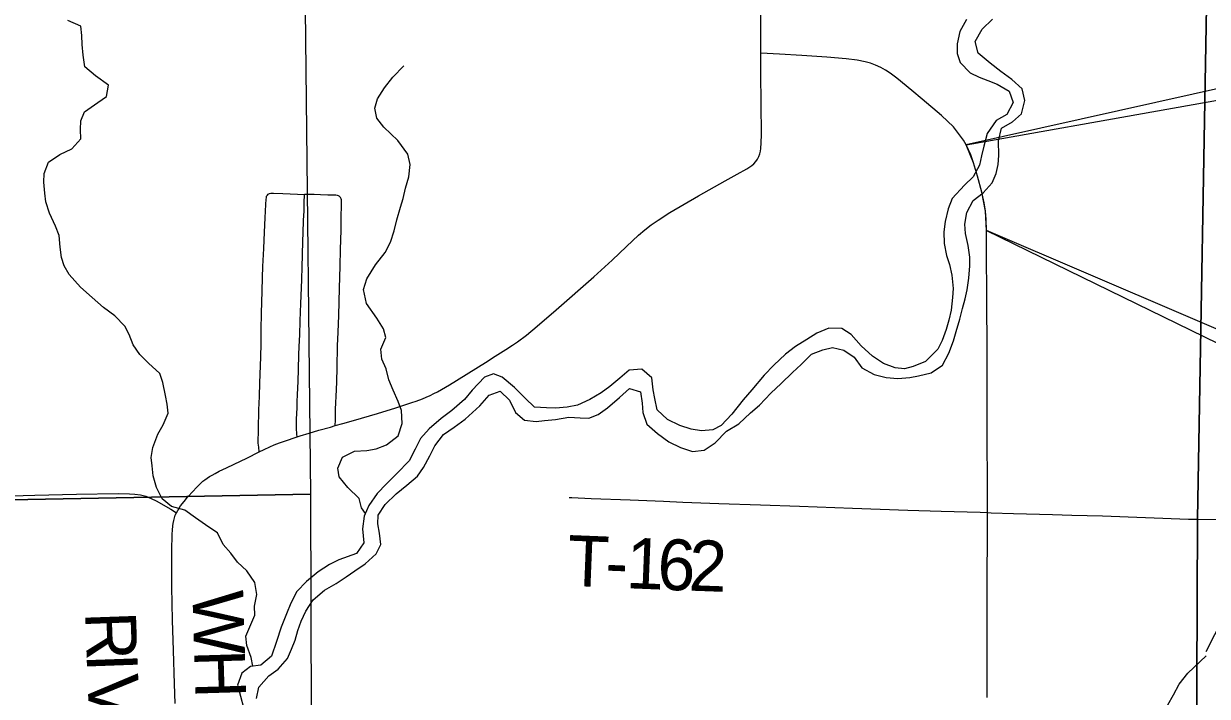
# Model space of a CAD drawing. Extents: x 0 to 45.9, y 0 to 22.
# Drawn here: x 4.156 to 5.48, y 17.508 to 18.26 of the extents above; entities that cross this region are included whole.
import ezdxf

# ---------------------------------------------------------------- set-up
doc = ezdxf.new("R2010")
doc.units = 0
for name, color, linetype in [('Default', 7, 'Continuous'), ('GM_X_County_Road', 7, 'Continuous'), ('GM_X_County_Road_Text', 7, 'Continuous'), ('GM_X_Major_River', 7, 'Continuous'), ('GM_X_Minor_River', 7, 'Continuous'), ('GM_X_Section', 7, 'Continuous'), ('GM_X_State_Route', 7, 'Continuous'), ('GM_X_Township_Road', 7, 'Continuous'), ('GM_X_Township_Road_Text', 7, 'Continuous'), ('SH_Border', 7, 'Continuous'), ('SH_Cut_Line', 7, 'Continuous'), ('SH_Text', 7, 'Continuous')]:
    doc.layers.add(name, color=color, linetype=linetype)

msp = doc.modelspace()

# ---------------------------------------------------------------- linework, layer by layer
at = {"layer": 'Default'}
msp.add_lwpolyline([(2.1, 19.7114), (2.1, 14.1), (5.4538, 14.1), (5.4606, 15.6588), (5.4651, 16.7018), (5.4694, 17.7061), (5.4802, 18.3214), (5.4737, 18.7216), (5.4752, 19.0482), (5.4759, 19.2109), (5.4773, 19.7108), (5.0826, 19.712), (3.7367, 19.7072), (2.15, 19.7113)], close=True, dxfattribs=at)
msp.add_lwpolyline([(5.4773, 19.7108), (5.4759, 19.2109), (5.4752, 19.0482), (5.4737, 18.7216), (5.4802, 18.3214), (5.4694, 17.7061), (5.4651, 16.7018), (5.4606, 15.6588), (5.4538, 14.1)], dxfattribs=at)
at = {"layer": 'GM_X_County_Road'}
for points in [[(4.5046, 17.8103), (4.5131, 17.8127), (4.5251, 17.816), (4.5519, 17.8239), (4.5727, 17.8303), (4.5905, 17.836), (4.5952, 17.8377), (4.6023, 17.8402), (4.6065, 17.842), (4.6109, 17.844), (4.6152, 17.8462), (4.6191, 17.8482), (4.6326, 17.856), (4.673, 17.8809), (4.6836, 17.8878), (4.6954, 17.8953), (4.7029, 17.9001), (4.7087, 17.9041), (4.7188, 17.9115), (4.7308, 17.9213), (4.752, 17.9396), (4.7939, 17.9766), (4.8146, 17.9954), (4.8304, 18.0104), (4.8439, 18.0231), (4.851, 18.0291), (4.8583, 18.0348), (4.8659, 18.0401), (4.879, 18.0484), (4.9112, 18.0671), (4.9409, 18.0839), (4.9545, 18.0914), (4.9653, 18.0975), (4.9706, 18.101), (4.9731, 18.1031), (4.9752, 18.1055), (4.9771, 18.1081), (4.9785, 18.111), (4.9796, 18.114), (4.9803, 18.1171), (4.9808, 18.1202), (4.9813, 18.1265), (4.9814, 18.1359), (4.9808, 18.2042), (4.9809, 18.2266)], [(4.4621, 17.7978), (4.4655, 17.7989), (4.4756, 17.8019), (4.4863, 17.8051), (4.4993, 17.8087), (4.5046, 17.8103)], [(4.4197, 17.7809), (4.4251, 17.7837), (4.4317, 17.7866), (4.4366, 17.7886), (4.4424, 17.7909), (4.448, 17.793), (4.4621, 17.7978)], [(4.327, 17.7129), (4.33, 17.718), (4.3318, 17.7205), (4.3357, 17.7254), (4.3396, 17.7301), (4.3457, 17.7371), (4.349, 17.7406), (4.3521, 17.7437), (4.3541, 17.7457), (4.3566, 17.748), (4.3588, 17.7496), (4.3615, 17.7516), (4.3641, 17.7532), (4.3669, 17.7547), (4.3705, 17.7568), (4.375, 17.7592), (4.383, 17.7631), (4.3915, 17.7671), (4.4057, 17.774), (4.4197, 17.7809)], [(3.7332, 17.7248), (3.8053, 17.7259), (3.8892, 17.7267), (3.9296, 17.7269), (3.9575, 17.7274), (4.0259, 17.7287), (4.1035, 17.7305), (4.1687, 17.7325), (4.2153, 17.7335), (4.262, 17.7342), (4.2744, 17.734), (4.2807, 17.7336), (4.2869, 17.7327), (4.29, 17.732), (4.293, 17.7312), (4.2989, 17.7289), (4.3046, 17.7261), (4.3207, 17.7167), (4.327, 17.7129)], [(4.3257, 17.4997), (4.3248, 17.5214), (4.3237, 17.5587), (4.3227, 17.5928), (4.3219, 17.63), (4.322, 17.6549), (4.322, 17.6704), (4.3225, 17.689), (4.3227, 17.6933), (4.3231, 17.6982), (4.3235, 17.7009), (4.3241, 17.7042), (4.3248, 17.7072), (4.3257, 17.71), (4.327, 17.7129)]]:
    msp.add_lwpolyline(points, dxfattribs=at)
at = {"layer": 'GM_X_Major_River'}
for points in [[(5.211, 18.2643), (5.2033, 18.2508), (5.2004, 18.2372), (5.2003, 18.2265), (5.2039, 18.2163), (5.2152, 18.2047), (5.225, 18.1997), (5.2348, 18.1961), (5.2453, 18.1922), (5.2585, 18.1844), (5.2633, 18.1714), (5.2559, 18.1583), (5.244, 18.1516), (5.234, 18.1369), (5.2304, 18.1226), (5.2276, 18.112), (5.2255, 18.1014), (5.2185, 18.0886), (5.2085, 18.0792), (5.195, 18.0642), (5.1903, 18.0525), (5.1871, 18.0386), (5.1854, 18.0268), (5.186, 18.0139), (5.1885, 18.0006), (5.1918, 17.9903), (5.1946, 17.9785), (5.196, 17.9637), (5.1954, 17.9535), (5.1937, 17.9394), (5.1913, 17.9281), (5.1881, 17.9179), (5.1838, 17.9054), (5.1787, 17.8956), (5.1649, 17.8818), (5.1511, 17.8763), (5.1416, 17.8738), (5.131, 17.8747), (5.1182, 17.8798), (5.1058, 17.8879), (5.093, 17.8994), (5.0818, 17.9121), (5.0716, 17.9187), (5.0569, 17.9193), (5.0435, 17.9138), (5.0324, 17.9067), (5.0198, 17.8989), (5.0083, 17.8903), (4.9952, 17.878), (4.9844, 17.8668), (4.9709, 17.8503), (4.9609, 17.839), (4.9485, 17.8229), (4.9366, 17.8105), (4.9271, 17.8057), (4.9145, 17.8044), (4.9028, 17.8064), (4.8903, 17.8104), (4.8764, 17.817), (4.8647, 17.8278), (4.8623, 17.8407), (4.8605, 17.8502), (4.8588, 17.8635), (4.8479, 17.8735), (4.8335, 17.8722), (4.8231, 17.8633), (4.812, 17.8539), (4.8024, 17.8468), (4.7894, 17.8394), (4.7757, 17.8332), (4.7642, 17.8307), (4.7513, 17.8297), (4.7411, 17.8302), (4.7278, 17.8308), (4.7173, 17.8408), (4.7053, 17.8527), (4.6915, 17.8646), (4.6817, 17.8682), (4.6717, 17.8645), (4.6579, 17.8499), (4.6494, 17.8394), (4.6352, 17.8271), (4.6233, 17.8181), (4.6099, 17.8066), (4.6002, 17.7957), (4.594, 17.784), (4.5874, 17.7708), (4.5735, 17.7566), (4.562, 17.745), (4.5516, 17.7345), (4.5423, 17.721), (4.5372, 17.7089), (4.5351, 17.6949), (4.5368, 17.6793), (4.5287, 17.6673)], [(4.5507, 17.667), (4.5557, 17.6772), (4.5544, 17.6901), (4.5523, 17.7004), (4.5528, 17.7102), (4.5605, 17.7219), (4.5728, 17.7338), (4.5847, 17.7435), (4.5966, 17.7536), (4.6036, 17.7634), (4.6106, 17.7766), (4.616, 17.7875), (4.6257, 17.8003), (4.6376, 17.8085), (4.6502, 17.8174), (4.6664, 17.8324), (4.6768, 17.8444), (4.6894, 17.8487), (4.6995, 17.8387), (4.7065, 17.825), (4.7166, 17.8165), (4.7295, 17.8148), (4.739, 17.8158), (4.7512, 17.8172), (4.766, 17.8196), (4.7789, 17.8191), (4.7884, 17.8186), (4.799, 17.8226), (4.8094, 17.83), (4.8228, 17.8416), (4.834, 17.8517), (4.8461, 17.8481), (4.8482, 17.8352), (4.8488, 17.825), (4.8532, 17.812), (4.8652, 17.8016), (4.8779, 17.7923), (4.8911, 17.7857), (4.9043, 17.7813), (4.9173, 17.7827), (4.9299, 17.7909), (4.9426, 17.804), (4.9564, 17.8121), (4.9694, 17.8245), (4.9794, 17.8331), (4.9921, 17.8466), (5.0036, 17.8574), (5.0163, 17.8698), (5.0259, 17.8787), (5.0375, 17.89), (5.0501, 17.8951), (5.0611, 17.8976), (5.0736, 17.8948), (5.0852, 17.8867), (5.0938, 17.8748), (5.1077, 17.8674), (5.121, 17.8642), (5.1342, 17.8629), (5.1475, 17.8642), (5.1574, 17.866), (5.1715, 17.8692), (5.1842, 17.8777), (5.1912, 17.8913), (5.1963, 17.9049), (5.1995, 17.9155), (5.2034, 17.9291), (5.2066, 17.9412), (5.2095, 17.9521), (5.2115, 17.962), (5.2136, 17.9752), (5.2145, 17.9889), (5.2146, 17.9987), (5.2129, 18.0116), (5.2097, 18.025), (5.2091, 18.0356), (5.2111, 18.0485), (5.2182, 18.062), (5.2297, 18.0706), (5.2397, 18.0819), (5.244, 18.092), (5.2464, 18.1022), (5.2469, 18.1121), (5.2468, 18.1288), (5.25, 18.1428), (5.2622, 18.1498), (5.2726, 18.1588), (5.2762, 18.1739), (5.273, 18.1869), (5.2617, 18.1973), (5.2493, 18.2062), (5.2373, 18.2154), (5.2238, 18.2266), (5.2206, 18.2396), (5.2283, 18.2535), (5.2399, 18.2647)], [(4.5287, 17.6673), (4.5088, 17.66), (4.4985, 17.6548), (4.4855, 17.6466), (4.4725, 17.6358), (4.4617, 17.6246), (4.4551, 17.6118), (4.4503, 17.5997), (4.4441, 17.585), (4.4389, 17.5687), (4.4334, 17.5525), (4.4215, 17.5424), (4.4101, 17.541), (4.4001, 17.5336), (4.3954, 17.52), (4.3986, 17.5078), (4.4022, 17.4949)], [(4.4168, 17.5053), (4.4193, 17.5178), (4.4304, 17.5305), (4.4408, 17.538), (4.4512, 17.55), (4.4559, 17.5601), (4.4598, 17.5703), (4.463, 17.5813), (4.4665, 17.5915), (4.472, 17.6028), (4.4802, 17.6156), (4.4928, 17.6264), (4.5058, 17.6338), (4.5169, 17.6413), (4.5265, 17.648), (4.5384, 17.6558), (4.5507, 17.667)]]:
    msp.add_lwpolyline(points, dxfattribs=at)
at = {"layer": 'GM_X_Minor_River'}
for points in [[(4.4126, 17.5413), (4.4106, 17.5509), (4.4058, 17.5642), (4.4048, 17.5749), (4.4103, 17.5877), (4.4147, 17.5983), (4.4144, 17.6085), (4.4169, 17.6214), (4.4148, 17.6347), (4.4058, 17.6477), (4.3953, 17.6577), (4.3879, 17.6677), (4.3793, 17.6773), (4.373, 17.6903), (4.3632, 17.6968), (4.3486, 17.7073), (4.3366, 17.7158), (4.3214, 17.7198), (4.3113, 17.7283), (4.3047, 17.7409), (4.301, 17.7542), (4.3001, 17.7652), (4.299, 17.7747), (4.3007, 17.7857), (4.3062, 17.8008), (4.3121, 17.8113), (4.3179, 17.8242), (4.3169, 17.8344), (4.3148, 17.8439), (4.3119, 17.8584), (4.3087, 17.8687), (4.2959, 17.8802), (4.2862, 17.8898), (4.2787, 17.9006), (4.2743, 17.912), (4.2695, 17.9215), (4.2583, 17.9331), (4.2455, 17.9424), (4.2328, 17.9535), (4.2197, 17.9651), (4.207, 17.9793), (4.2014, 17.9889), (4.1985, 17.9984), (4.1971, 18.0098), (4.1958, 18.0227), (4.1918, 18.0334), (4.1851, 18.0479), (4.1811, 18.0605), (4.1797, 18.07), (4.1788, 18.0825), (4.1793, 18.0923), (4.184, 18.1048), (4.1966, 18.1134), (4.21, 18.1196), (4.22, 18.1309), (4.2198, 18.1415), (4.2203, 18.151), (4.2242, 18.1612), (4.2392, 18.1716), (4.2487, 18.1783), (4.2512, 18.1908), (4.2365, 18.2012), (4.2245, 18.2116), (4.2228, 18.2245), (4.2218, 18.2363), (4.2212, 18.2466), (4.2202, 18.2568), (4.2055, 18.2631)], [(4.5386, 17.7121), (4.5343, 17.7184), (4.5314, 17.7287), (4.519, 17.741), (4.509, 17.7529), (4.5076, 17.7628), (4.513, 17.7749), (4.5264, 17.7815), (4.5401, 17.7825), (4.5504, 17.7842), (4.5622, 17.7886), (4.5752, 17.7987), (4.5796, 17.8127), (4.579, 17.8271), (4.575, 17.8374), (4.5695, 17.85), (4.5647, 17.8614), (4.5618, 17.8736), (4.557, 17.8847), (4.5557, 17.8957), (4.5612, 17.9089), (4.5586, 17.9184), (4.5512, 17.9303), (4.5397, 17.9467), (4.5365, 17.9623), (4.54, 17.9744), (4.5497, 17.9899), (4.5606, 18.0037), (4.5664, 18.0154), (4.5707, 18.0279), (4.5736, 18.0404), (4.5776, 18.0544), (4.5807, 18.0642), (4.5835, 18.0759), (4.5871, 18.0884), (4.5885, 18.1024), (4.586, 18.1138), (4.5748, 18.1291), (4.559, 18.1441), (4.5512, 18.1541), (4.5491, 18.1651), (4.5519, 18.1757), (4.56, 18.1881), (4.5693, 18.1998), (4.5816, 18.2125)], [(5.479, 17.5575), (5.4887, 17.5766), (5.4944, 17.5872), (5.5004, 17.5994), (5.5076, 17.6089), (5.5189, 17.6214), (5.5238, 17.6343), (5.5249, 17.648), (5.5256, 17.6677), (5.5267, 17.6795), (5.5278, 17.689), (5.5289, 17.7015), (5.5364, 17.7129), (5.55, 17.7197), (5.5622, 17.7255), (5.5667, 17.738), (5.5628, 17.7505), (5.5575, 17.7626)], [(5.4363, 17.498), (5.4425, 17.5093), (5.4487, 17.521), (5.4584, 17.5334), (5.4789, 17.5528)]]:
    msp.add_lwpolyline(points, dxfattribs=at)
at = {"layer": 'GM_X_Section'}
for points in [[(3.4889, 18.7329), (4.4658, 18.7509), (4.477, 17.7336), (3.4888, 17.7149)], [(3.4888, 17.7149), (4.477, 17.7336), (4.4801, 16.7228), (3.479, 16.7029)]]:
    msp.add_lwpolyline(points, close=True, dxfattribs=at)
at = {"layer": 'GM_X_State_Route'}
for points in [[(5.1613, 18.1753), (5.1497, 18.1851), (5.1328, 18.1988), (5.1254, 18.2043), (5.1202, 18.2077), (5.1149, 18.2107), (5.1093, 18.2133), (5.1036, 18.2154), (5.0977, 18.2171), (5.0886, 18.2189), (5.0763, 18.2205), (5.0547, 18.2224), (5.0268, 18.2242), (5.0019, 18.2256), (4.9809, 18.2266), (4.9808, 18.2836)], [(5.2332, 17.9954), (5.2331, 18.0005), (5.2331, 18.0284), (5.2328, 18.0408), (5.232, 18.0501), (5.2306, 18.0592), (5.2279, 18.0713), (5.2231, 18.0893), (5.2187, 18.1042), (5.2156, 18.1129), (5.2132, 18.1186), (5.2104, 18.1241), (5.2074, 18.1294), (5.2021, 18.137), (5.1963, 18.1442), (5.1898, 18.1508), (5.183, 18.1571), (5.1613, 18.1753)], [(5.2342, 17.5063), (5.2341, 17.5405), (5.2341, 17.5591), (5.2341, 17.6058), (5.2342, 17.6369), (5.2345, 17.6897), (5.2344, 17.713), (5.2344, 17.7394), (5.2342, 17.8016), (5.2339, 17.842), (5.2339, 17.8576), (5.234, 17.8793), (5.2339, 17.9103), (5.2337, 17.9352), (5.2335, 17.9632), (5.2332, 17.9954)]]:
    msp.add_lwpolyline(points, dxfattribs=at)
at = {"layer": 'GM_X_Township_Road'}
for points in [[(4.4197, 17.7809), (4.4191, 17.786), (4.4187, 17.7908), (4.4189, 17.8063), (4.4194, 17.8279), (4.4199, 17.8429), (4.4203, 17.858), (4.4214, 17.8868), (4.4218, 17.9019), (4.422, 17.9173), (4.4224, 17.9359), (4.4228, 17.9482), (4.4231, 17.9606), (4.4235, 17.976), (4.4239, 17.9882), (4.4247, 18.0084), (4.4255, 18.0265), (4.4263, 18.0425), (4.427, 18.0574), (4.4275, 18.0636), (4.4277, 18.0648), (4.428, 18.0667), (4.4289, 18.0681), (4.4298, 18.069), (4.4313, 18.0698), (4.4327, 18.0702), (4.4357, 18.0703), (4.4462, 18.0698), (4.4625, 18.069), (4.4703, 18.0687)], [(4.4621, 17.7978), (4.4618, 17.8006), (4.4616, 17.8027), (4.4615, 17.8055), (4.4614, 17.808), (4.4615, 17.8184), (4.4617, 17.8227), (4.4621, 17.8311), (4.4623, 17.837), (4.4626, 17.8449), (4.4631, 17.8595), (4.4636, 17.8732), (4.4642, 17.8893), (4.4644, 17.8987), (4.465, 17.9118), (4.4655, 17.9274), (4.4663, 17.9468), (4.4671, 17.9642), (4.4673, 17.9738), (4.4677, 17.9878), (4.468, 18.0008), (4.4684, 18.017), (4.4688, 18.0256), (4.4694, 18.0401), (4.4698, 18.05), (4.4701, 18.0593), (4.4703, 18.0687)], [(4.5046, 17.8103), (4.5049, 17.8165), (4.5052, 17.8288), (4.506, 17.8503), (4.5064, 17.8594), (4.5068, 17.8748), (4.5074, 17.8994), (4.5079, 17.9148), (4.5086, 17.9333), (4.5091, 17.9486), (4.5094, 17.964), (4.5101, 17.9886), (4.5106, 18.0072), (4.5112, 18.0289), (4.5113, 18.0349), (4.5113, 18.0409), (4.5114, 18.0471), (4.5116, 18.0532), (4.5119, 18.0593), (4.5119, 18.0604), (4.5119, 18.0613), (4.5117, 18.0627), (4.5114, 18.0639), (4.5108, 18.0652), (4.5099, 18.0662), (4.5093, 18.0667), (4.5085, 18.0672), (4.5073, 18.0676), (4.5055, 18.0678), (4.5023, 18.0678), (4.4992, 18.0679), (4.4963, 18.068), (4.4883, 18.0683), (4.481, 18.0685), (4.4753, 18.0686), (4.4703, 18.0687)], [(4.7664, 17.7298), (4.7693, 17.7299), (4.791, 17.7289), (4.8345, 17.7272), (4.8718, 17.7256), (4.8936, 17.7246), (4.934, 17.723), (4.9806, 17.7215), (5.0242, 17.7202), (5.0832, 17.7181), (5.1454, 17.7158), (5.1827, 17.7146), (5.2263, 17.7134), (5.2344, 17.713)], [(5.2344, 17.713), (5.2386, 17.7127), (5.2635, 17.7121), (5.3071, 17.7107), (5.3288, 17.7102), (5.363, 17.7092), (5.4594, 17.7057), (5.4696, 17.7055)], [(5.4696, 17.7055), (5.5009, 17.7053), (5.5666, 17.7064), (5.6884, 17.7097), (5.7415, 17.711), (5.7497, 17.7112)]]:
    msp.add_lwpolyline(points, dxfattribs=at)
at = {"layer": 'SH_Border'}
for points in [[(9.5057, 19.0827), (5.2104, 18.1241), (9.5057, 18.8875)], [(9.4963, 16.2045), (5.2331, 18.0284), (9.4963, 15.9502)]]:
    msp.add_lwpolyline(points, close=True, dxfattribs=at)
at = {"layer": 'SH_Cut_Line'}
msp.add_lwpolyline([(5.2331, 18.0284), (5.232, 18.0501), (5.2279, 18.0713), (5.2231, 18.0893), (5.2187, 18.1042), (5.2104, 18.1241)], dxfattribs=at)
at = {"layer": 'SH_Text'}
for points in [[(5.4538, 14.1), (5.4606, 15.6588), (5.4651, 16.7018), (5.4694, 17.7061), (5.4802, 18.3214), (5.4737, 18.7216), (5.4752, 19.0482), (5.4759, 19.2109), (5.4773, 19.7108)], [(5.4773, 19.7108), (5.4759, 19.2109), (5.4752, 19.0482), (5.4737, 18.7216), (5.4802, 18.3214), (5.4694, 17.7061), (5.4651, 16.7018), (5.4606, 15.6588), (5.4538, 14.1)]]:
    msp.add_lwpolyline(points, dxfattribs=at)

# ---------------------------------------------------------------- texts
at = {"layer": 'GM_X_County_Road_Text'}
for s, rotation, p in [('W', 271.688, (4.3449, 17.6251)), ('R', 272.0339, (4.2249, 17.6017)), ('I', 272.0589, (4.2265, 17.555)), ('H', 271.7204, (4.3468, 17.5593)), ('V', 272.2709, (4.2274, 17.5315))]:
    msp.add_text(s, height=0.0568, rotation=rotation, dxfattribs=at).set_placement(p)
at = {"layer": 'GM_X_Township_Road_Text'}
for s, rotation, p in [('T', 357.7109, (4.7636, 17.6312)), ('1', 357.7155, (4.8294, 17.6285)), ('6', 357.7466, (4.8644, 17.6271)), ('2', 357.9278, (4.8996, 17.6258)), ('-', 357.7092, (4.8061, 17.6295))]:
    msp.add_text(s, height=0.0568, rotation=rotation, dxfattribs=at).set_placement(p)

doc.saveas('drawing.dxf')
